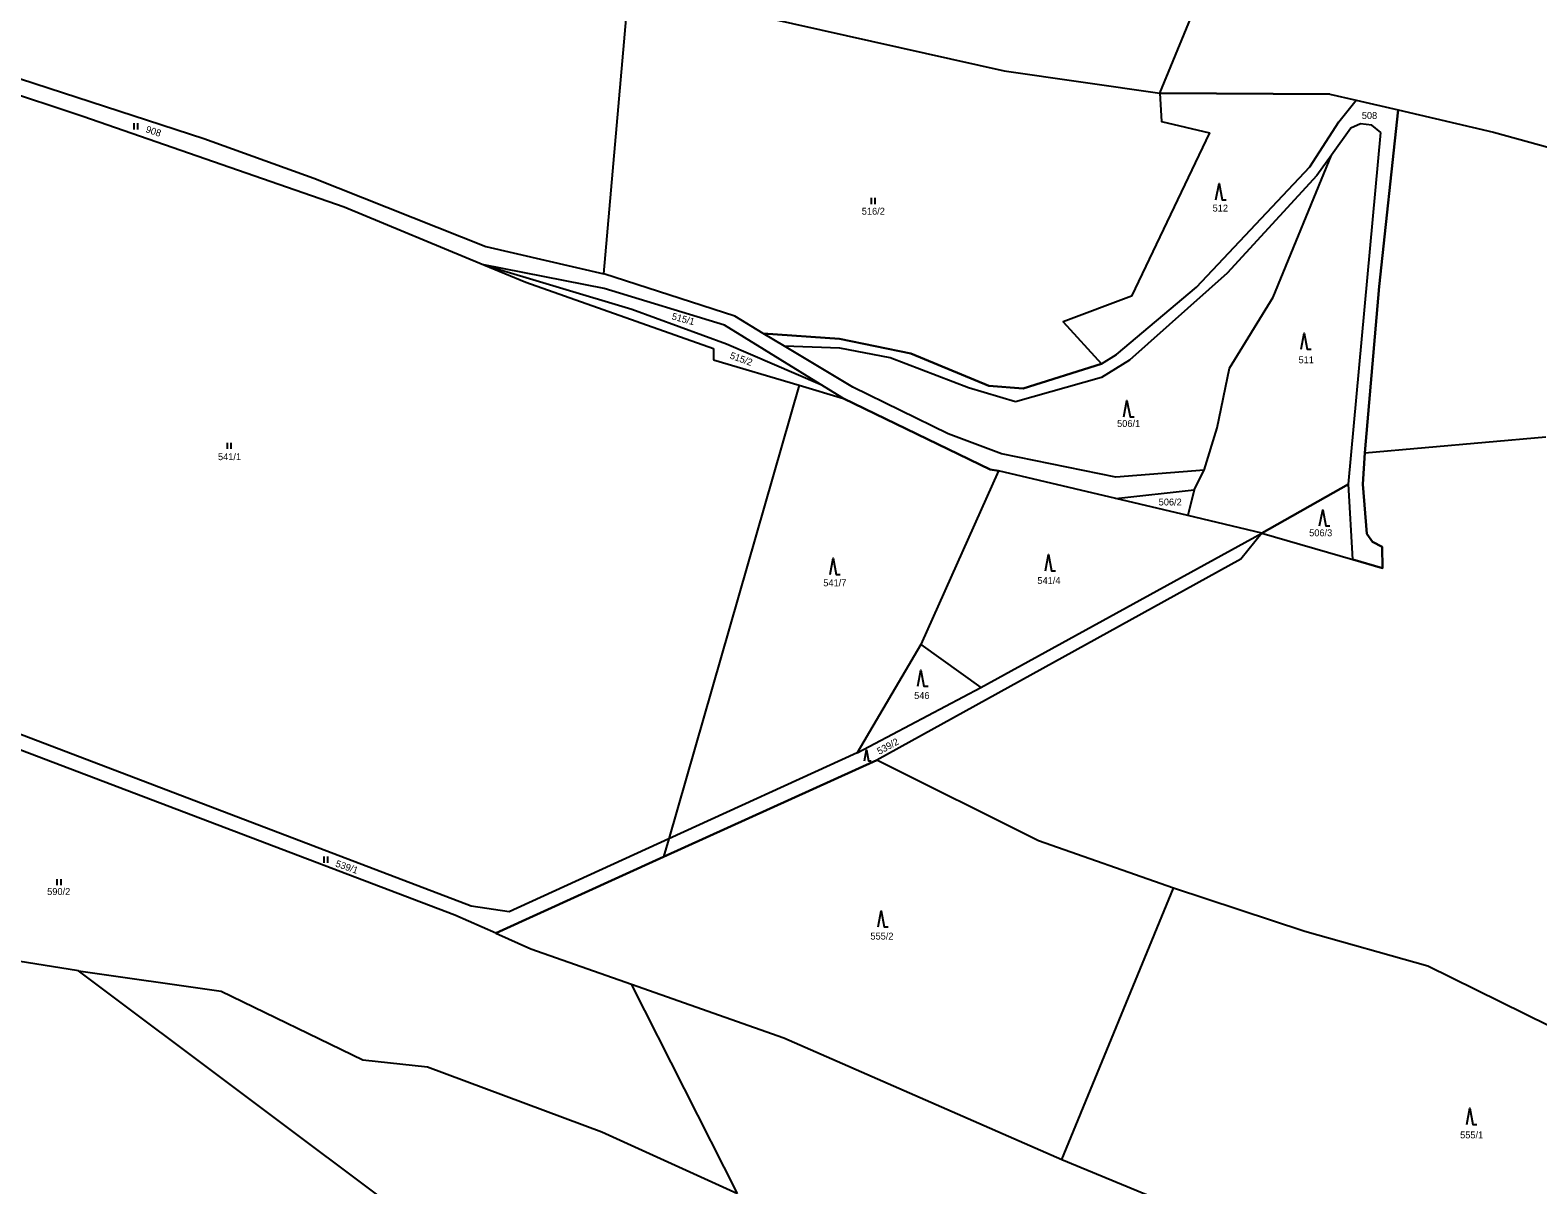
# Model space of a CAD drawing. Extents: x -580551 to -575069, y -1073031 to -1067931.
# Drawn here: x -577749.4 to -577377.7, y -1070721.5 to -1070436.8 of the extents above; entities that cross this region are included whole.
import ezdxf

# ---------------------------------------------------------------- set-up
doc = ezdxf.new("R2010")
doc.units = 0
for name, color, linetype in [('Druh pozemku', 7, 'Continuous'), ('Hranice z DKM', 7, 'Continuous'), ('Parcela', 7, 'Continuous'), ('Parcelní číslo', 7, 'Continuous'), ('Vrstva 6', 7, 'Continuous')]:
    doc.layers.add(name, color=color, linetype=linetype)

msp = doc.modelspace()

# ---------------------------------------------------------------- linework, layer by layer
at = {"layer": 'Druh pozemku'}
for p, q in [((-577723.79, -1070459.76), (-577723.79, -1070461.26)), ((-577722.79, -1070461.26), (-577722.79, -1070459.76)), ((-577542.04, -1070478.17), (-577542.04, -1070479.67)), ((-577541.04, -1070479.67), (-577541.04, -1070478.17)), ((-577700.77, -1070538.56), (-577700.77, -1070540.06)), ((-577699.77, -1070540.06), (-577699.77, -1070538.56)), ((-577676.98, -1070640.54), (-577676.98, -1070642.04)), ((-577675.98, -1070642.04), (-577675.98, -1070640.54)), ((-577742.74, -1070646.1), (-577742.74, -1070647.6)), ((-577741.74, -1070647.6), (-577741.74, -1070646.1))]:
    msp.add_line(p, q, dxfattribs=at)
for points in [[(-577457.03, -1070478.61), (-577456.28, -1070474.61), (-577455.53, -1070478.61), (-577454.53, -1070478.61)], [(-577436.05, -1070515.47), (-577435.3, -1070511.47), (-577434.55, -1070515.47), (-577433.55, -1070515.47)], [(-577479.72, -1070532.13), (-577478.97, -1070528.13), (-577478.22, -1070532.13), (-577477.22, -1070532.13)], [(-577431.48, -1070559.04), (-577430.73, -1070555.04), (-577429.98, -1070559.04), (-577428.98, -1070559.04)], [(-577499.08, -1070570.11), (-577498.33, -1070566.11), (-577497.58, -1070570.11), (-577496.58, -1070570.11)], [(-577552.14, -1070571.01), (-577551.39, -1070567.01), (-577550.64, -1070571.01), (-577549.64, -1070571.01)], [(-577530.52, -1070598.56), (-577529.77, -1070594.56), (-577529.02, -1070598.56), (-577528.02, -1070598.56)], [(-577543.712, -1070616.94), (-577543.21, -1070614.26), (-577542.708, -1070616.94), (-577542.038, -1070616.94)], [(-577540.33, -1070657.88), (-577539.58, -1070653.88), (-577538.83, -1070657.88), (-577537.83, -1070657.88)], [(-577395.2, -1070706.58), (-577394.45, -1070702.58), (-577393.7, -1070706.58), (-577392.7, -1070706.58)]]:
    msp.add_lwpolyline(points, dxfattribs=at)
at = {"layer": 'Hranice z DKM'}
msp.add_line((-577549.83, -1070512.94), (-577568.63, -1070511.55), dxfattribs=at)
for points in [[(-577470.88, -1070452.36), (-577470.48, -1070459.34), (-577458.67, -1070462.16), (-577477.86, -1070502.36), (-577494.72, -1070508.71), (-577485.28, -1070519.05), (-577504.6, -1070525.17), (-577513, -1070524.45), (-577532.22, -1070516.56), (-577549.83, -1070512.94)], [(-577470.88, -1070452.36), (-577428.94, -1070452.55), (-577422.5, -1070454.06), (-577412.11, -1070456.49), (-577416.83, -1070500.03), (-577420.34, -1070540.98), (-577420.85, -1070548.75), (-577419.81, -1070561), (-577418.47, -1070562.91), (-577416.09, -1070564.22), (-577415.99, -1070569.42), (-577423.29, -1070567.31), (-577424.35, -1070548.76), (-577445.74, -1070560.81), (-577464.01, -1070556.48), (-577481.68, -1070552.3), (-577462.37, -1070550.1), (-577459.95, -1070545.3), (-577481.69, -1070547.01)], [(-577481.69, -1070547.01), (-577509.92, -1070541.22), (-577523.09, -1070536.3), (-577546.59, -1070524.78), (-577563.39, -1070514.69)], [(-577481.68, -1070552.3), (-577510.62, -1070545.44), (-577512.72, -1070545.09), (-577548.85, -1070527.58)], [(-577445.74, -1070560.81), (-577450.91, -1070567.19), (-577540.6, -1070616.73)], [(-577634.53, -1070659.39), (-577593.24, -1070640.64), (-577540.6, -1070616.73)]]:
    msp.add_lwpolyline(points, dxfattribs=at)
at = {"layer": 'Parcela'}
for p, q in [((-577470.88, -1070452.36), (-577451.04, -1070404.2)), ((-577607.92, -1070496.9), (-577601.89, -1070427.79)), ((-577567.64, -1070433.75), (-577509.21, -1070446.82)), ((-577791.25, -1070439.87), (-577736.35, -1070458)), ((-577509.21, -1070446.82), (-577470.88, -1070452.36)), ((-577755.23, -1070447.68), (-577706.55, -1070463.5)), ((-577428.94, -1070452.55), (-577470.88, -1070452.36)), ((-577470.88, -1070452.36), (-577470.48, -1070459.34)), ((-577428.94, -1070452.55), (-577422.5, -1070454.06)), ((-577426.78, -1070459.38), (-577422.5, -1070454.06)), ((-577422.5, -1070454.06), (-577412.11, -1070456.49)), ((-577736.35, -1070458), (-577671.94, -1070480.36)), ((-577416.83, -1070500.03), (-577412.11, -1070456.49)), ((-577412.11, -1070456.49), (-577388.61, -1070461.98)), ((-577458.67, -1070462.16), (-577477.86, -1070502.36)), ((-577470.48, -1070459.34), (-577458.67, -1070462.16)), ((-577433.89, -1070470.47), (-577426.78, -1070459.38)), ((-577423.8, -1070460.96), (-577428.57, -1070467.61)), ((-577424.35, -1070548.76), (-577416.43, -1070462.02)), ((-577421.39, -1070459.91), (-577423.8, -1070460.96)), ((-577418.59, -1070460.24), (-577421.39, -1070459.91)), ((-577416.43, -1070462.02), (-577418.59, -1070460.24)), ((-577388.61, -1070461.98), (-577318.64, -1070481.21)), ((-577706.55, -1070463.5), (-577679.44, -1070473.3)), ((-577428.57, -1070467.61), (-577432.18, -1070472.64)), ((-577679.44, -1070473.3), (-577637.01, -1070490.13)), ((-577461.86, -1070500.18), (-577433.89, -1070470.47)), ((-577432.18, -1070472.64), (-577454.31, -1070496.7)), ((-577671.94, -1070480.36), (-577637.49, -1070494.66)), ((-577637.01, -1070490.13), (-577607.92, -1070496.9)), ((-577607.83, -1070500.46), (-577637.49, -1070494.66)), ((-577637.49, -1070494.66), (-577627.18, -1070498.94)), ((-577627.18, -1070498.94), (-577580.87, -1070515.29)), ((-577575.66, -1070507.32), (-577607.92, -1070496.9)), ((-577454.31, -1070496.7), (-577478.34, -1070518.19)), ((-577578.22, -1070509.56), (-577607.83, -1070500.46)), ((-577477.86, -1070502.36), (-577494.72, -1070508.71)), ((-577481.57, -1070516.74), (-577461.86, -1070500.18)), ((-577420.34, -1070540.98), (-577416.83, -1070500.03)), ((-577554.63, -1070524.04), (-577578.22, -1070509.56)), ((-577568.63, -1070511.55), (-577575.66, -1070507.32)), ((-577494.72, -1070508.71), (-577485.28, -1070519.05)), ((-577568.63, -1070511.55), (-577549.83, -1070512.94)), ((-577563.39, -1070514.69), (-577568.63, -1070511.55)), ((-577549.83, -1070512.94), (-577532.22, -1070516.56)), ((-577580.87, -1070515.29), (-577580.9, -1070518.1)), ((-577549.79, -1070515.23), (-577563.39, -1070514.69)), ((-577546.59, -1070524.78), (-577563.39, -1070514.69)), ((-577537.36, -1070517.58), (-577549.79, -1070515.23)), ((-577518.02, -1070524.98), (-577537.36, -1070517.58)), ((-577532.22, -1070516.56), (-577513, -1070524.45)), ((-577485.28, -1070519.05), (-577481.57, -1070516.74)), ((-577580.9, -1070518.1), (-577559.75, -1070524.36)), ((-577504.6, -1070525.17), (-577485.28, -1070519.05)), ((-577478.34, -1070518.19), (-577485.29, -1070522.41)), ((-577559.75, -1070524.36), (-577591.95, -1070636.17)), ((-577559.75, -1070524.36), (-577548.85, -1070527.58)), ((-577548.85, -1070527.58), (-577554.63, -1070524.04)), ((-577523.09, -1070536.3), (-577546.59, -1070524.78)), ((-577506.44, -1070528.45), (-577518.02, -1070524.98)), ((-577513, -1070524.45), (-577504.6, -1070525.17)), ((-577485.29, -1070522.41), (-577506.44, -1070528.45)), ((-577548.85, -1070527.58), (-577512.72, -1070545.09)), ((-577509.92, -1070541.22), (-577523.09, -1070536.3)), ((-577420.34, -1070540.98), (-577375.71, -1070537.09)), ((-577481.69, -1070547.01), (-577509.92, -1070541.22)), ((-577420.85, -1070548.75), (-577420.34, -1070540.98)), ((-577510.62, -1070545.44), (-577529.8, -1070588.23)), ((-577512.72, -1070545.09), (-577510.62, -1070545.44)), ((-577481.68, -1070552.3), (-577510.62, -1070545.44)), ((-577459.95, -1070545.3), (-577481.69, -1070547.01)), ((-577462.37, -1070550.1), (-577459.95, -1070545.3)), ((-577481.68, -1070552.3), (-577462.37, -1070550.1)), ((-577423.29, -1070567.31), (-577424.35, -1070548.76)), ((-577419.81, -1070561), (-577420.85, -1070548.75)), ((-577464.01, -1070556.48), (-577481.68, -1070552.3)), ((-577445.74, -1070560.81), (-577464.01, -1070556.48)), ((-577515.02, -1070598.82), (-577445.74, -1070560.81)), ((-577445.74, -1070560.81), (-577450.91, -1070567.19)), ((-577445.74, -1070560.81), (-577423.29, -1070567.31)), ((-577418.47, -1070562.91), (-577419.81, -1070561)), ((-577416.09, -1070564.22), (-577418.47, -1070562.91)), ((-577415.99, -1070569.42), (-577416.09, -1070564.22)), ((-577450.91, -1070567.19), (-577540.6, -1070616.73)), ((-577423.29, -1070567.31), (-577415.99, -1070569.42)), ((-577529.8, -1070588.23), (-577545.5, -1070614.93)), ((-577529.8, -1070588.23), (-577515.02, -1070598.82)), ((-577545.5, -1070614.93), (-577515.02, -1070598.82)), ((-577644.65, -1070654.99), (-577763.03, -1070609.98)), ((-577640.62, -1070652.74), (-577759.37, -1070607.53)), ((-577540.6, -1070616.73), (-577593.24, -1070640.64)), ((-577545.5, -1070614.93), (-577591.95, -1070636.17)), ((-577500.8, -1070636.62), (-577540.6, -1070616.73)), ((-577591.95, -1070636.17), (-577631.27, -1070654.15)), ((-577591.95, -1070636.17), (-577593.24, -1070640.64)), ((-577467.51, -1070648.35), (-577500.8, -1070636.62)), ((-577593.24, -1070640.64), (-577634.53, -1070659.39)), ((-577495.05, -1070715.24), (-577467.51, -1070648.35)), ((-577435.17, -1070658.99), (-577467.51, -1070648.35)), ((-577634.53, -1070659.39), (-577644.65, -1070654.99)), ((-577631.27, -1070654.15), (-577640.62, -1070652.74)), ((-577404.82, -1070667.59), (-577435.17, -1070658.99)), ((-577634.53, -1070659.39), (-577625.94, -1070663.27)), ((-577737.46, -1070668.67), (-577756.39, -1070665.66)), ((-577625.94, -1070663.27), (-577601.14, -1070672)), ((-577737.46, -1070668.67), (-577702.26, -1070673.73)), ((-577622.28, -1070754.97), (-577737.46, -1070668.67)), ((-577374.97, -1070682.23), (-577404.82, -1070667.59)), ((-577702.26, -1070673.73), (-577667.37, -1070690.63)), ((-577601.14, -1070672), (-577563.58, -1070685.23)), ((-577575, -1070723.62), (-577601.14, -1070672)), ((-577563.58, -1070685.23), (-577495.05, -1070715.24)), ((-577667.37, -1070690.63), (-577651.39, -1070692.34)), ((-577651.39, -1070692.34), (-577608.41, -1070708.37)), ((-577608.41, -1070708.37), (-577575, -1070723.62)), ((-577495.05, -1070715.24), (-577412.14, -1070749.3))]:
    msp.add_line(p, q, dxfattribs=at)
at = {"layer": 'Vrstva 6'}
for p, q in [((-577442.96, -1070502.62), (-577428.57, -1070467.61)), ((-577637.49, -1070494.66), (-577601.03, -1070505.57)), ((-577453.66, -1070520.1), (-577442.96, -1070502.62)), ((-577601.03, -1070505.57), (-577577.66, -1070514.16)), ((-577577.66, -1070514.16), (-577554.63, -1070524.04)), ((-577456.73, -1070534.88), (-577453.66, -1070520.1)), ((-577459.95, -1070545.3), (-577456.73, -1070534.88)), ((-577462.37, -1070550.1), (-577464.01, -1070556.48)), ((-577445.74, -1070560.81), (-577424.35, -1070548.76))]:
    msp.add_line(p, q, dxfattribs=at)

# ---------------------------------------------------------------- texts
at = {"layer": 'Parcelní číslo'}
for s, p in [('508', (-577421.087, -1070458.7)), ('516/2', (-577544.349, -1070482.3)), ('512', (-577457.864, -1070481.53)), ('511', (-577436.681, -1070518.92)), ('506/1', (-577481.407, -1070534.63)), ('541/1', (-577703.046, -1070542.81)), ('506/2', (-577471.159, -1070553.98)), ('506/3', (-577434.061, -1070561.57)), ('541/7', (-577553.838, -1070573.9)), ('541/4', (-577501.054, -1070573.34)), ('546', (-577531.436, -1070601.68)), ('590/2', (-577745.159, -1070650)), ('555/2', (-577542.218, -1070661)), ('555/1', (-577396.846, -1070710))]:
    msp.add_text(s, height=1.7, dxfattribs=at).set_placement(p)
for s, rotation, p in [('908', 342.0558, (-577721, -1070461.956)), ('515/1', 345.03518, (-577591.323, -1070508.095)), ('515/2', 340.22234, (-577577.021, -1070517.689)), ('539/2', 28.70519, (-577540.018, -1070615.463)), ('539/1', 340.68071, (-577674.23, -1070642.95))]:
    msp.add_text(s, height=1.7, rotation=rotation, dxfattribs=at).set_placement(p)

doc.saveas('drawing.dxf')
